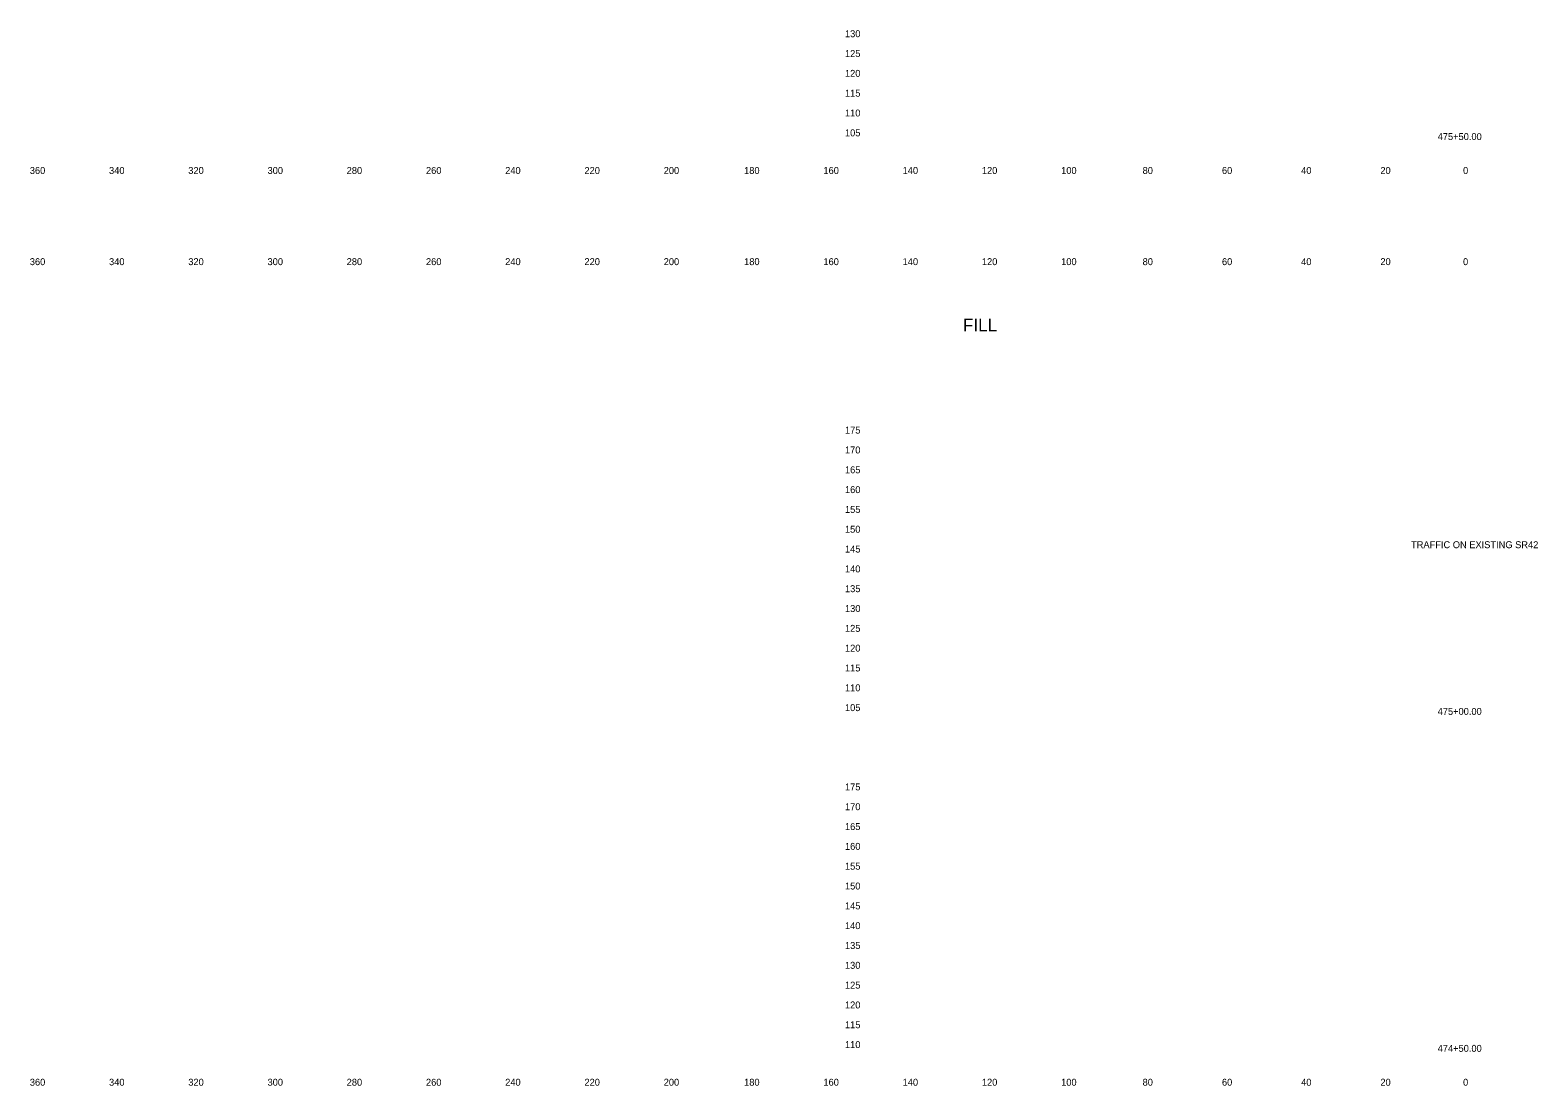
# Model space of a CAD drawing. Extents: x 21281 to 22024, y 6472 to 15198.
# Drawn here: x 21280.5 to 21661, y 10845.3 to 11111.6 of the extents above; entities that cross this region are included whole.
import ezdxf

# ---------------------------------------------------------------- set-up
doc = ezdxf.new("R2010")
doc.units = 0
for name, color, linetype in [('XS_SHEET_LABELS_ELEVATION', 7, 'Continuous'), ('XS_SHEET_LABELS_OFFSET', 7, 'Continuous'), ('XS_SHEET_LABELS_STATION', 7, 'Continuous')]:
    doc.layers.add(name, color=color, linetype=linetype)

msp = doc.modelspace()

# ---------------------------------------------------------------- texts
at = {"layer": 'XS_SHEET_LABELS_ELEVATION'}
for s, p in [('  130  ', (21484.84, 11109.84)), ('  125  ', (21484.84, 11104.84)), ('  120  ', (21484.84, 11099.84)), ('  115  ', (21484.84, 11094.84)), ('  110  ', (21484.84, 11089.84)), ('  105  ', (21484.84, 11084.84)), ('  175  ', (21484.84, 11009.84)), ('  170  ', (21484.84, 11004.84)), ('  165  ', (21484.84, 10999.84)), ('  160  ', (21484.84, 10994.84)), ('  155  ', (21484.84, 10989.84)), ('  150  ', (21484.84, 10984.84)), ('  145  ', (21484.84, 10979.84)), ('  140  ', (21484.84, 10974.84)), ('  135  ', (21484.84, 10969.84)), ('  130  ', (21484.84, 10964.84)), ('  125  ', (21484.84, 10959.84)), ('  120  ', (21484.84, 10954.84)), ('  115  ', (21484.84, 10949.84)), ('  110  ', (21484.84, 10944.84)), ('  105  ', (21484.84, 10939.84)), ('  175  ', (21484.84, 10919.84)), ('  170  ', (21484.84, 10914.84)), ('  165  ', (21484.84, 10909.84)), ('  160  ', (21484.84, 10904.84)), ('  155  ', (21484.84, 10899.84)), ('  150  ', (21484.84, 10894.84)), ('  145  ', (21484.84, 10889.84)), ('  140  ', (21484.84, 10884.84)), ('  135  ', (21484.84, 10879.84)), ('  130  ', (21484.84, 10874.84)), ('  125  ', (21484.84, 10869.84)), ('  120  ', (21484.84, 10864.84)), ('  115  ', (21484.84, 10859.84)), ('  110  ', (21484.84, 10854.84))]:
    msp.add_text(s, height=1.75, dxfattribs=at).set_placement(p)
at = {"layer": 'XS_SHEET_LABELS_OFFSET'}
for s, height, p in [('  360  ', 1.75, (21279.14, 11075.34)), ('  340  ', 1.75, (21299.13, 11075.34)), ('  320  ', 1.75, (21319.13, 11075.34)), ('  300  ', 1.75, (21339.13, 11075.34)), ('  280  ', 1.75, (21359.1, 11075.34)), ('  260  ', 1.75, (21379.11, 11075.34)), ('  240  ', 1.75, (21399.1, 11075.34)), ('  220  ', 1.75, (21419.1, 11075.34)), ('  200  ', 1.75, (21439.1, 11075.34)), ('  180  ', 1.75, (21459.39, 11075.34)), ('  160  ', 1.75, (21479.4, 11075.34)), ('  140  ', 1.75, (21499.39, 11075.34)), ('  120  ', 1.75, (21519.39, 11075.34)), ('  100  ', 1.75, (21539.39, 11075.34)), ('  80  ', 1.75, (21559.95, 11075.34)), ('  60  ', 1.75, (21579.97, 11075.34)), ('  40  ', 1.75, (21599.95, 11075.34)), ('  20  ', 1.75, (21619.95, 11075.34)), ('  0  ', 1.75, (21640.81, 11075.34)), ('  0  ', 1.75, (21640.81, 11075.34)), ('  360  ', 1.75, (21279.14, 11052.34)), ('  340  ', 1.75, (21299.13, 11052.34)), ('  320  ', 1.75, (21319.13, 11052.34)), ('  300  ', 1.75, (21339.13, 11052.34)), ('  280  ', 1.75, (21359.1, 11052.34)), ('  260  ', 1.75, (21379.11, 11052.34)), ('  240  ', 1.75, (21399.1, 11052.34)), ('  220  ', 1.75, (21419.1, 11052.34)), ('  200  ', 1.75, (21439.1, 11052.34)), ('  180  ', 1.75, (21459.39, 11052.34)), ('  160  ', 1.75, (21479.4, 11052.34)), ('  140  ', 1.75, (21499.39, 11052.34)), ('  120  ', 1.75, (21519.39, 11052.34)), ('  100  ', 1.75, (21539.39, 11052.34)), ('  80  ', 1.75, (21559.95, 11052.34)), ('  60  ', 1.75, (21579.97, 11052.34)), ('  40  ', 1.75, (21599.95, 11052.34)), ('  20  ', 1.75, (21619.95, 11052.34)), ('  0  ', 1.75, (21640.81, 11052.34)), ('  0  ', 1.75, (21640.81, 11052.34)), ('FILL', 3.222, (21515.91, 11035.6)), ('  360  ', 1.75, (21279.14, 10845.34)), ('  340  ', 1.75, (21299.13, 10845.34)), ('  320  ', 1.75, (21319.13, 10845.34)), ('  300  ', 1.75, (21339.13, 10845.34)), ('  280  ', 1.75, (21359.1, 10845.34)), ('  260  ', 1.75, (21379.11, 10845.34)), ('  240  ', 1.75, (21399.1, 10845.34)), ('  220  ', 1.75, (21419.1, 10845.34)), ('  200  ', 1.75, (21439.1, 10845.34)), ('  180  ', 1.75, (21459.39, 10845.34)), ('  160  ', 1.75, (21479.4, 10845.34)), ('  140  ', 1.75, (21499.39, 10845.34)), ('  120  ', 1.75, (21519.39, 10845.34)), ('  100  ', 1.75, (21539.39, 10845.34)), ('  80  ', 1.75, (21559.95, 10845.34)), ('  60  ', 1.75, (21579.97, 10845.34)), ('  40  ', 1.75, (21599.95, 10845.34)), ('  20  ', 1.75, (21619.95, 10845.34)), ('  0  ', 1.75, (21640.81, 10845.34)), ('  0  ', 1.75, (21640.81, 10845.34))]:
    msp.add_text(s, height=height, dxfattribs=at).set_placement(p)
at = {"layer": 'XS_SHEET_LABELS_STATION'}
for s, p in [('  475+50.00  ', (21634.4, 11083.89)), ('TRAFFIC ON EXISTING SR42', (21628.99, 10980.94)), ('  475+00.00  ', (21634.4, 10938.89)), ('  474+50.00  ', (21634.4, 10853.89))]:
    msp.add_text(s, height=1.75, dxfattribs=at).set_placement(p)

doc.saveas('drawing.dxf')
